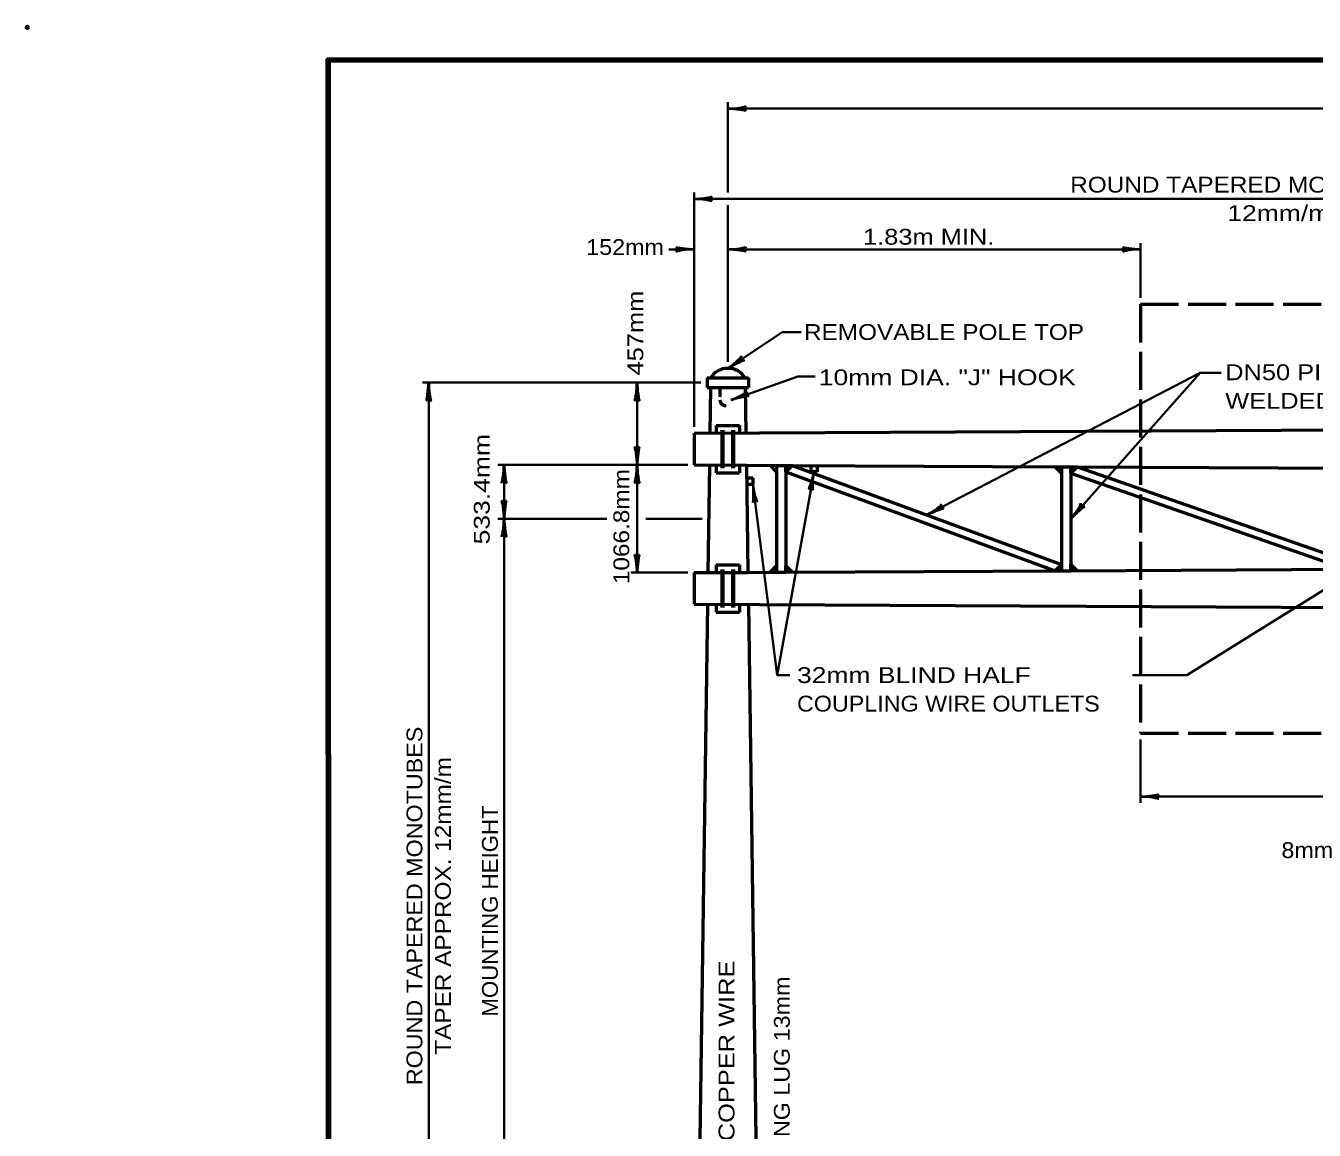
# Model space of a CAD drawing. Extents: x -34 to 822, y -23 to 521.
# Drawn here: x -34.1 to 210.1, y 311.9 to 521.1 of the extents above; entities that cross this region are included whole.
import ezdxf
from ezdxf.enums import TextEntityAlignment as Align

# ---------------------------------------------------------------- set-up
doc = ezdxf.new("R2010")
doc.units = 0
doc.header["$LTSCALE"] = 1.2
doc.header["$PDMODE"] = 32
doc.header["$PDSIZE"] = 0.6
doc.linetypes.add('LONG_DASHED', pattern=[7.5, 6, -1.5])
doc.linetypes.add('SHORT_DASHED', pattern=[2.7, 1.5, -1.2])
doc.layers.add('1', color=7, linetype='Continuous', lineweight=35)

msp = doc.modelspace()

# ---------------------------------------------------------------- linework, layer by layer
at = {"layer": '1'}
for p, q in [((98.952, 489.542), (98.952, 506.642)), ((98.952, 505.442), (565.548, 505.442)), ((92.55, 445.142), (92.55, 489.542)), ((98.952, 457.442), (98.952, 487.142)), ((92.55, 478.781), (87.75, 478.781)), ((177.161, 478.781), (98.952, 478.781)), ((177.161, 469.567), (177.161, 479.981)), ((188.431, 455.402), (192.433, 455.402)), ((93.852, 453.542), (41.052, 453.542)), ((42.252, 453.542), (42.252, 255.991)), ((91.35, 437.942), (55.35, 437.942)), ((56.55, 437.942), (56.55, 427.741)), ((246.392, 435.773), (185.926, 398.114)), ((76.011, 427.741), (55.35, 427.741)), ((56.55, 427.741), (56.55, 255.991)), ((94.099, 427.741), (83.412, 427.741)), ((91.35, 417.542), (80.55, 417.542)), ((108.28, 398.114), (110.708, 398.114)), ((185.926, 398.114), (175.621, 398.114)), ((177.161, 385.917), (177.161, 373.917)), ((177.161, 375.117), (487.338, 375.308))]:
    msp.add_line(p, q, dxfattribs=at)
at = {"layer": '1', "linetype": 'LONG_DASHED', "lineweight": 53}
for p, q in [((177.161, 468.367), (177.161, 387.117)), ((177.161, 468.367), (487.338, 468.367)), ((177.161, 387.117), (487.338, 387.308))]:
    msp.add_line(p, q, dxfattribs=at)
at = {"layer": '1', "lineweight": 53}
for p, q in [((95.052, 454.442), (102.852, 454.442)), ((95.052, 454.442), (95.052, 452.642)), ((102.852, 454.442), (102.852, 452.642)), ((95.652, 452.642), (95.529, 443.957)), ((102.252, 452.642), (102.375, 443.991)), ((92.55, 443.942), (331.35, 445.142)), ((96.75, 445.442), (101.154, 445.442)), ((96.75, 445.442), (96.75, 443.963)), ((101.154, 445.442), (101.154, 443.985)), ((92.55, 443.942), (92.55, 437.942)), ((92.55, 437.942), (102.462, 437.892)), ((95.443, 437.927), (95.154, 417.555)), ((96.75, 437.921), (96.75, 436.442)), ((101.154, 437.899), (101.154, 436.442)), ((102.461, 437.892), (102.75, 417.593)), ((102.462, 437.892), (108.161, 437.863)), ((108.161, 436.663), (106.962, 437.869)), ((108.161, 437.863), (109.961, 437.854)), ((108.161, 437.863), (108.161, 417.62)), ((109.961, 437.854), (162.161, 437.592)), ((109.961, 437.854), (109.961, 417.629)), ((111.161, 437.848), (162.161, 419.091)), ((114.676, 437.82), (114.676, 436.62)), ((115.876, 437.82), (115.876, 436.62)), ((160.961, 437.598), (162.161, 437.592)), ((162.161, 436.392), (160.962, 437.598)), ((162.161, 437.592), (163.961, 437.583)), ((162.161, 437.592), (162.161, 417.892)), ((162.161, 437.592), (162.161, 436.392)), ((163.961, 437.583), (217.361, 437.315)), ((163.961, 437.583), (163.961, 417.901)), ((165.161, 437.577), (217.361, 419.369)), ((96.75, 436.442), (101.154, 436.442)), ((102.496, 435.492), (103.696, 435.492)), ((103.696, 435.492), (103.696, 434.292)), ((109.961, 436.654), (160.962, 417.886)), ((115.876, 436.62), (114.676, 436.62)), ((163.961, 436.383), (216.162, 418.163)), ((102.496, 434.292), (103.696, 434.292)), ((92.55, 417.542), (102.75, 417.593)), ((92.55, 417.542), (92.55, 411.542)), ((96.75, 419.042), (101.154, 419.042)), ((96.75, 419.042), (96.75, 417.563)), ((101.154, 419.042), (101.154, 417.585)), ((102.75, 417.593), (108.161, 417.62)), ((108.161, 417.62), (109.961, 417.629)), ((109.961, 417.629), (162.161, 417.892)), ((111.161, 417.636), (109.961, 417.629)), ((162.161, 417.892), (163.961, 417.901)), ((163.961, 419.101), (165.161, 417.907)), ((163.961, 417.901), (217.361, 418.169)), ((92.55, 411.542), (331.35, 410.342)), ((95.069, 411.529), (92.995, 265.442)), ((96.75, 411.521), (96.75, 410.042)), ((101.154, 411.499), (101.154, 410.042)), ((102.836, 411.49), (104.91, 265.442)), ((96.75, 410.042), (101.154, 410.042))]:
    msp.add_line(p, q, dxfattribs=at)
at = {"layer": '1', "linetype": 'SHORT_DASHED', "lineweight": 53}
msp.add_line((97.452, 452.642), (97.452, 450.242), dxfattribs=at)
at = {"layer": '1', "lineweight": 70}
for p, q in [((97.95, 444.542), (97.95, 437.342)), ((99.954, 444.542), (99.954, 437.342)), ((97.95, 418.142), (97.95, 410.942)), ((99.954, 418.142), (99.954, 410.942))]:
    msp.add_line(p, q, dxfattribs=at)
at = {"layer": '1', "lineweight": 158}
msp.add_lwpolyline([(814.9, 514.74), (23.2, 514.64), (23.3, -11.36)], dxfattribs=at)
at = {"layer": '1'}
for points in [[(92.55, 488.342), (332.25, 488.342), (571.95, 488.342)], [(98.952, 456.242), (109.254, 463.063), (112.829, 463.063)], [(99.552, 450.242), (112.207, 454.667), (115.471, 454.667)], [(136.661, 428.47), (188.431, 455.402), (163.961, 427.742)], [(81.75, 417.542), (81.75, 437.942), (81.75, 453.542)], [(103.696, 434.292), (108.28, 398.114), (115.276, 436.62)]]:
    msp.add_lwpolyline(points, dxfattribs=at)
at = {"layer": '1', "lineweight": 53}
for points in [[(95.052, 452.642), (95.652, 452.642), (102.852, 452.642)], [(106.961, 437.869), (108.161, 437.863), (108.161, 436.663)], [(109.961, 417.629), (109.961, 418.829), (111.161, 417.635)], [(165.161, 417.907), (163.961, 417.901), (163.961, 419.101)]]:
    msp.add_lwpolyline(points, dxfattribs=at)
for points in [[(109.961, 436.654), (109.961, 437.854), (111.161, 437.848)], [(163.961, 436.383), (163.961, 437.583), (165.161, 437.577)], [(106.962, 417.614), (108.161, 418.82), (108.161, 417.62), (106.961, 417.614)], [(160.962, 417.886), (162.161, 419.091), (162.161, 417.892), (160.961, 417.885)]]:
    msp.add_lwpolyline(points, close=True, dxfattribs=at)
msp.add_arc((98.952, 452.364), 3.878, 32.40314, 147.59687, dxfattribs=at)
at = {"layer": '1', "linetype": 'SHORT_DASHED', "lineweight": 53}
msp.add_arc((98.502, 450.241), 1.05, 179.93556, 0.06444, dxfattribs=at)
at = {"layer": '1', "lineweight": 40}
for centre, major_axis, ratio, start_param, end_param in [((100.297, 505.188), (-2.108, 0.211), 0.07063, 3.1407148, 5.41811), ((100.297, 505.188), (-2.108, 0.211), 0.07063, 3.1407148, 5.41811), ((100.262, 505.773), (-2.143, -0.187), 0.122415, 0.8963533, 3.1415927), ((100.262, 505.773), (-2.143, -0.187), 0.122415, 0.8963533, 3.1415927), ((93.859, 488.673), (-2.143, -0.187), 0.122415, 0.8963533, 3.1415927), ((93.859, 488.673), (-2.143, -0.187), 0.122415, 0.8963533, 3.1415927), ((93.895, 488.088), (-2.108, 0.211), 0.07063, 3.1407148, 5.41811), ((93.895, 488.088), (-2.108, 0.211), 0.07063, 3.1407148, 5.41811), ((91.24, 478.449), (2.143, 0.187), 0.122415, 0.8963533, 3.1415927), ((91.205, 479.035), (2.108, -0.211), 0.07063, 3.1407148, 5.41811), ((100.297, 478.527), (-2.108, 0.211), 0.07063, 3.1407148, 5.41811), ((100.297, 478.527), (-2.108, 0.211), 0.07063, 3.1407148, 5.41811), ((100.262, 479.112), (-2.143, -0.187), 0.122415, 0.8963533, 3.1415927), ((100.262, 479.112), (-2.143, -0.187), 0.122415, 0.8963533, 3.1415927), ((175.852, 478.449), (2.143, 0.187), 0.122415, 0.8963533, 3.1415927), ((175.852, 478.449), (2.143, 0.187), 0.122415, 0.8963533, 3.1415927), ((175.817, 479.035), (2.108, -0.211), 0.07063, 3.1407148, 5.41811), ((175.817, 479.035), (2.108, -0.211), 0.07063, 3.1407148, 5.41811), ((99.861, 457.241), (-1.683, -1.339), 0.122415, 0.8963533, 3.1415927), ((99.861, 457.241), (-1.683, -1.339), 0.122415, 0.8963533, 3.1415927), ((100.213, 456.772), (-1.874, -0.988), 0.07063, 3.1407148, 5.41811), ((100.213, 456.772), (-1.874, -0.988), 0.07063, 3.1407148, 5.41811), ((41.998, 452.197), (0.211, 2.108), 0.07063, 3.1407148, 5.41811), ((41.998, 452.197), (0.211, 2.108), 0.07063, 3.1407148, 5.41811), ((42.584, 452.232), (-0.187, 2.143), 0.122415, 0.8963533, 3.1415927), ((42.584, 452.232), (-0.187, 2.143), 0.122415, 0.8963533, 3.1415927), ((81.496, 452.197), (0.211, 2.108), 0.07063, 3.1407148, 5.41811), ((81.496, 452.197), (0.211, 2.108), 0.07063, 3.1407148, 5.41811), ((82.081, 452.232), (-0.187, 2.143), 0.122415, 0.8963533, 3.1415927), ((82.081, 452.232), (-0.187, 2.143), 0.122415, 0.8963533, 3.1415927), ((100.679, 450.987), (-1.961, -0.884), 0.122415, 0.8963533, 3.1415927), ((100.679, 450.987), (-1.961, -0.884), 0.122415, 0.8963533, 3.1415927), ((100.905, 450.446), (2.059, 0.497), 0.07063, 6.2823074, 8.5597026), ((100.905, 450.446), (2.059, 0.497), 0.07063, 6.2823074, 8.5597026), ((81.418, 439.251), (0.187, -2.143), 0.122415, 0.8963533, 3.1415927), ((81.418, 439.251), (0.187, -2.143), 0.122415, 0.8963533, 3.1415927), ((82.004, 439.286), (-0.211, -2.108), 0.07063, 3.1407148, 5.41811), ((82.004, 439.286), (-0.211, -2.108), 0.07063, 3.1407148, 5.41811), ((56.296, 436.597), (0.211, 2.108), 0.07063, 3.1407148, 5.41811), ((56.296, 436.597), (0.211, 2.108), 0.07063, 3.1407148, 5.41811), ((56.881, 436.632), (-0.187, 2.143), 0.122415, 0.8963533, 3.1415927), ((56.881, 436.632), (-0.187, 2.143), 0.122415, 0.8963533, 3.1415927), ((81.496, 436.597), (0.211, 2.108), 0.07063, 3.1407148, 5.41811), ((81.496, 436.597), (0.211, 2.108), 0.07063, 3.1407148, 5.41811), ((82.081, 436.632), (-0.187, 2.143), 0.122415, 0.8963533, 3.1415927), ((82.081, 436.632), (-0.187, 2.143), 0.122415, 0.8963533, 3.1415927), ((56.218, 429.051), (0.187, -2.143), 0.122415, 0.8963533, 3.1415927), ((56.218, 429.051), (0.187, -2.143), 0.122415, 0.8963533, 3.1415927), ((56.804, 429.086), (-0.211, -2.108), 0.07063, 3.1407148, 5.41811), ((56.804, 429.086), (-0.211, -2.108), 0.07063, 3.1407148, 5.41811), ((137.67, 429.368), (-1.815, -1.155), 0.122415, 0.8963533, 3.1415927), ((137.67, 429.368), (-1.815, -1.155), 0.122415, 0.8963533, 3.1415927), ((164.581, 428.942), (-1.279, -1.729), 0.122415, 0.8963533, 3.1415927), ((164.581, 428.942), (-1.279, -1.729), 0.122415, 0.8963533, 3.1415927), ((165.042, 428.581), (1.554, 1.439), 0.07063, 6.2823074, 8.5597026), ((165.042, 428.581), (1.554, 1.439), 0.07063, 6.2823074, 8.5597026), ((56.296, 426.396), (0.211, 2.108), 0.07063, 3.1407148, 5.41811), ((56.296, 426.396), (0.211, 2.108), 0.07063, 3.1407148, 5.41811), ((56.881, 426.432), (-0.187, 2.143), 0.122415, 0.8963533, 3.1415927), ((56.881, 426.432), (-0.187, 2.143), 0.122415, 0.8963533, 3.1415927), ((137.971, 428.865), (1.967, 0.786), 0.07063, 6.2823074, 8.5597026), ((137.971, 428.865), (1.967, 0.786), 0.07063, 6.2823074, 8.5597026), ((81.418, 418.851), (0.187, -2.143), 0.122415, 0.8963533, 3.1415927), ((81.418, 418.851), (0.187, -2.143), 0.122415, 0.8963533, 3.1415927), ((82.004, 418.886), (-0.211, -2.108), 0.07063, 3.1407148, 5.41811), ((82.004, 418.886), (-0.211, -2.108), 0.07063, 3.1407148, 5.41811), ((178.505, 374.863), (-2.108, 0.209), 0.07063, 3.1407148, 5.41811), ((178.505, 374.863), (-2.108, 0.209), 0.07063, 3.1407148, 5.41811), ((178.47, 375.449), (-2.143, -0.189), 0.122415, 0.8963533, 3.1415927), ((178.47, 375.449), (-2.143, -0.189), 0.122415, 0.8963533, 3.1415927)]:
    msp.add_ellipse(centre, major_axis=major_axis, ratio=ratio, start_param=start_param, end_param=end_param, dxfattribs=at)
at = {"layer": '1'}
for centre, major_axis, ratio, start_param, end_param in [((114.786, 435.342), (-0.584, -2.036), 0.07063, 6.2823074, 8.5597026), ((114.786, 435.342), (-0.584, -2.036), 0.07063, 6.2823074, 8.5597026), ((115.368, 435.272), (0.199, 2.142), 0.122415, 0.8963533, 3.1415927), ((115.368, 435.272), (0.199, 2.142), 0.122415, 0.8963533, 3.1415927), ((103.613, 432.926), (-0.056, 2.118), 0.07063, 3.1407148, 5.41811), ((103.613, 432.926), (-0.056, 2.118), 0.07063, 3.1407148, 5.41811), ((104.189, 433.035), (-0.455, 2.102), 0.122415, 0.8963533, 3.1415927), ((104.189, 433.035), (-0.455, 2.102), 0.122415, 0.8963533, 3.1415927)]:
    msp.add_ellipse(centre, major_axis=major_axis, ratio=ratio, start_param=start_param, end_param=end_param, dxfattribs=at)
msp.add_point((-33.8, 520.84), dxfattribs=at)

# ---------------------------------------------------------------- texts
for s, width, p in [('ROUND TAPERED MONOTUBE 12.19m MAX.', 1.15, (212.4, 489.542)), ('12mm/m TAPER', 1.25, (212.4, 484.142)), ('8mm', 1.1, (208.757, 363.47))]:
    msp.add_text(s, height=3, dxfattribs=dict(at, width=width)).set_placement(p, align=Align.CENTER)
for s, width, p in [('1.83m MIN.', 1.2, (124.565, 479.671)), ('152mm', 1.1, (72.111, 477.72)), ('REMOVABLE POLE TOP', 1.15, (113.371, 461.619)), ('DN50 PIPE (ENDS SLOTTED)', 1.2, (193.195, 453.999)), ('10mm DIA. "J" HOOK', 1.25, (116.181, 453.042)), ('WELDED TO 13mm PL. GUSSETS', 1.2, (193.195, 448.599)), ('32mm BLIND HALF', 1.25, (112.052, 396.62)), ('COUPLING WIRE OUTLETS', 1.1, (112.052, 391.221))]:
    msp.add_text(s, height=3, dxfattribs=dict(at, width=width)).set_placement(p)
for s, width, p in [('457mm', 1.2, (82.92, 454.9)), ('533.4mm', 1.25, (53.811, 422.889)), ('1066.8mm', 1.15, (80.257, 415.355)), ('MOUNTING HEIGHT', 1.05, (55.358, 333.424)), (' 4 AWG COPPER WIRE', 1.2, (100.196, 291.622)), ('GROUNDING LUG 13mm', 1.1, (110.677, 289.764))]:
    msp.add_text(s, height=3, rotation=90, dxfattribs=dict(at, width=width)).set_placement(p)
for s, width, p in [('ROUND TAPERED MONOTUBES', 1.1, (41.052, 354.392)), ('TAPER APPROX. 12mm/m', 1.15, (46.452, 354.392))]:
    msp.add_text(s, height=3, rotation=90, dxfattribs=dict(at, width=width)).set_placement(p, align=Align.CENTER)

doc.saveas('drawing.dxf')
